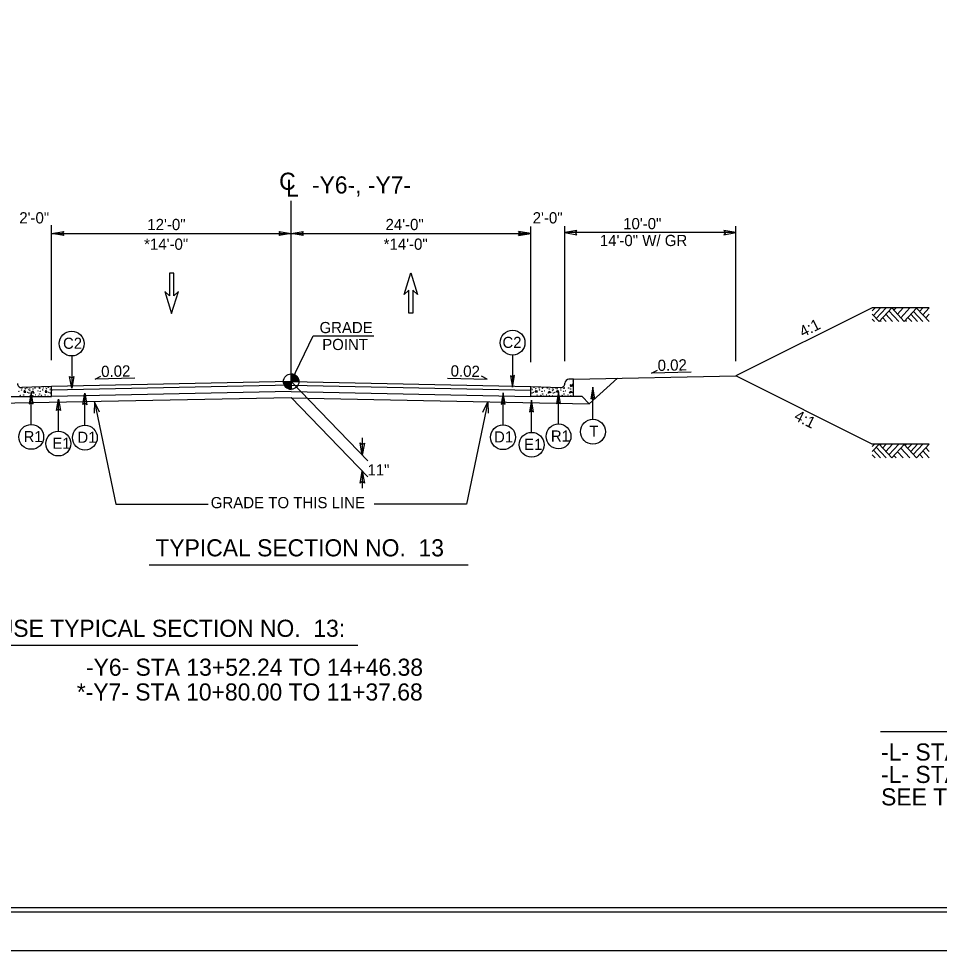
# Model space of a CAD drawing. Extents: x 1901670 to 1902225, y 193498 to 194278.
# Drawn here: x 1902009.7 to 1902063.5, y 193498 to 193552.5 of the extents above; entities that cross this region are included whole.
import ezdxf

# ---------------------------------------------------------------- set-up
doc = ezdxf.new("R2010")
doc.units = 0
for name, color, linetype in [('Old_Level_1', 7, 'Continuous'), ('Old_Level_11', 7, 'Continuous'), ('Old_Level_2', 7, 'Continuous'), ('Old_Level_20', 7, 'Continuous'), ('Prop Dimension', 7, 'Continuous'), ('Sheet Border Standard 30in CELL', 7, 'Continuous'), ('Sheet Cutting Line CELL', 7, 'Continuous'), ('Sheet Plot Border Inside CELL', 7, 'Continuous'), ('Sheet Plot Border Outside CELL', 7, 'Continuous'), ('Typical Curb CELL', 7, 'Continuous'), ('Typical Pavement Slope CELL', 7, 'Continuous'), ('Typical Terminator CELL', 7, 'Continuous'), ('Typical Text Grade Point CELL', 7, 'Continuous')]:
    doc.layers.add(name, color=color, linetype=linetype)

# ---------------------------------------------------------------- blocks, each defined once
blk = doc.blocks.new('TERMINATOR')
at = {"layer": 'Typical Terminator CELL'}
blk.add_lwpolyline([(-0.469, 0.081), (0, 0), (-0.471, -0.083), (-0.411, 0)], close=True, dxfattribs=at)

msp = doc.modelspace()

# ---------------------------------------------------------------- linework, layer by layer
at = {"layer": 'Old_Level_1'}
for p, q in [((1902025.621, 193531.249), (1902025.621, 193541.807)), ((1902059.748, 193535.554), (1902059.578, 193535.371)), ((1902060.068, 193535.554), (1902059.654, 193535.11)), ((1902060.401, 193535.554), (1902059.821, 193534.931)), ((1902060.723, 193535.553), (1902059.982, 193534.757)), ((1902061.144, 193534.749), (1902060.558, 193535.377)), ((1902061.454, 193534.767), (1902060.723, 193535.553)), ((1902060.987, 193535.554), (1902060.854, 193535.411)), ((1902061.389, 193535.554), (1902061.056, 193535.195)), ((1902061.787, 193535.554), (1902061.254, 193534.981)), ((1902062.178, 193535.546), (1902061.454, 193534.767)), ((1902062.546, 193534.749), (1902061.992, 193535.345)), ((1902062.92, 193534.749), (1902062.178, 193535.546)), ((1902062.545, 193535.554), (1902062.358, 193535.353)), ((1902062.92, 193535.554), (1902062.545, 193535.151)), ((1902059.982, 193534.757), (1902059.578, 193535.192)), ((1902059.712, 193534.749), (1902059.578, 193534.892)), ((1902060.113, 193534.749), (1902060.044, 193534.823)), ((1902060.408, 193534.749), (1902060.191, 193534.982)), ((1902060.774, 193534.749), (1902060.374, 193535.178)), ((1902061.579, 193534.749), (1902061.508, 193534.825)), ((1902061.89, 193534.749), (1902061.663, 193534.992)), ((1902062.237, 193534.749), (1902061.836, 193535.178)), ((1902062.92, 193535.192), (1902062.714, 193534.97)), ((1902014.167, 193531.391), (1902014.5, 193531.558)), ((1902016.482, 193531.44), (1902014.167, 193531.391)), ((1902025.621, 193531.249), (1902025.621, 193531.699)), ((1902034.759, 193531.44), (1902037.074, 193531.391)), ((1902037.074, 193531.391), (1902036.741, 193531.558)), ((1902044.701, 193531.437), (1902043.043, 193529.952)), ((1902046.691, 193531.746), (1902047.024, 193531.913)), ((1902049.006, 193531.794), (1902046.691, 193531.746)), ((1902025.621, 193531.249), (1902011.621, 193530.969)), ((1902025.621, 193531.03), (1902011.621, 193530.75)), ((1902025.171, 193531.249), (1902025.621, 193531.249)), ((1902025.62, 193530.799), (1902025.621, 193531.249)), ((1902025.621, 193531.249), (1902025.62, 193530.799)), ((1902025.621, 193531.249), (1902030.097, 193526.624)), ((1902026.071, 193531.249), (1902025.621, 193531.249)), ((1902025.621, 193531.249), (1902039.621, 193530.969)), ((1902025.621, 193531.03), (1902039.621, 193530.75)), ((1902025.621, 193530.301), (1902008.198, 193529.952)), ((1902025.621, 193530.665), (1902011.621, 193530.385)), ((1902025.621, 193530.665), (1902039.621, 193530.385)), ((1902025.621, 193530.301), (1902043.043, 193529.952)), ((1902025.623, 193530.314), (1902030.099, 193525.689)), ((1902042.62, 193530.375), (1902042.12, 193530.385)), ((1902042.62, 193530.375), (1902043.043, 193529.952)), ((1902029.778, 193527.953), (1902029.778, 193526.953)), ((1902059.712, 193527.597), (1902059.578, 193527.454)), ((1902059.982, 193527.589), (1902059.578, 193527.154)), ((1902060.723, 193526.793), (1902059.982, 193527.589)), ((1902060.113, 193527.597), (1902060.044, 193527.523)), ((1902060.408, 193527.597), (1902060.191, 193527.364)), ((1902060.774, 193527.597), (1902060.374, 193527.168)), ((1902061.144, 193527.597), (1902060.558, 193526.969)), ((1902061.579, 193527.597), (1902061.508, 193527.521)), ((1902061.89, 193527.597), (1902061.663, 193527.354)), ((1902062.237, 193527.597), (1902061.836, 193527.168)), ((1902062.546, 193527.597), (1902061.992, 193527.001)), ((1902062.92, 193527.597), (1902062.178, 193526.8)), ((1902060.068, 193526.792), (1902059.654, 193527.236)), ((1902060.401, 193526.792), (1902059.821, 193527.415)), ((1902061.454, 193527.579), (1902060.723, 193526.793)), ((1902061.389, 193526.792), (1902061.056, 193527.151)), ((1902061.787, 193526.792), (1902061.254, 193527.365)), ((1902062.178, 193526.8), (1902061.454, 193527.579)), ((1902062.92, 193526.792), (1902062.545, 193527.195)), ((1902062.92, 193527.154), (1902062.714, 193527.376)), ((1902059.748, 193526.792), (1902059.578, 193526.975)), ((1902060.987, 193526.792), (1902060.854, 193526.935)), ((1902062.545, 193526.792), (1902062.358, 193526.993)), ((1902029.78, 193526.019), (1902029.78, 193525.019))]:
    msp.add_line(p, q, dxfattribs=at)
for points in [[(1902025.625, 193531.699), (1902025.625, 193531.699), (1902025.625, 193531.249)], [(1902025.634, 193531.699), (1902025.634, 193531.249)], [(1902025.643, 193531.698), (1902025.643, 193531.249)], [(1902025.652, 193531.698), (1902025.652, 193531.249)], [(1902025.661, 193531.697), (1902025.661, 193531.249)], [(1902025.67, 193531.696), (1902025.67, 193531.249)], [(1902025.679, 193531.695), (1902025.679, 193531.249)], [(1902025.688, 193531.694), (1902025.688, 193531.249)], [(1902025.697, 193531.693), (1902025.697, 193531.249)], [(1902025.706, 193531.691), (1902025.706, 193531.249)], [(1902025.715, 193531.689), (1902025.715, 193531.249)], [(1902025.724, 193531.687), (1902025.724, 193531.249)], [(1902025.733, 193531.685), (1902025.733, 193531.249)], [(1902025.742, 193531.682), (1902025.742, 193531.249)], [(1902025.751, 193531.68), (1902025.751, 193531.249)], [(1902025.76, 193531.677), (1902025.76, 193531.249)], [(1902025.769, 193531.674), (1902025.769, 193531.249)], [(1902025.778, 193531.671), (1902025.778, 193531.249)], [(1902025.787, 193531.667), (1902025.787, 193531.249)], [(1902025.796, 193531.663), (1902025.796, 193531.249)], [(1902025.805, 193531.659), (1902025.805, 193531.249)], [(1902025.814, 193531.655), (1902025.814, 193531.249)], [(1902025.823, 193531.651), (1902025.823, 193531.249)], [(1902025.832, 193531.646), (1902025.832, 193531.249)], [(1902025.841, 193531.641), (1902025.841, 193531.249)], [(1902025.85, 193531.636), (1902025.85, 193531.249)], [(1902025.859, 193531.631), (1902025.859, 193531.249)], [(1902025.868, 193531.625), (1902025.868, 193531.249)], [(1902025.877, 193531.619), (1902025.877, 193531.249)], [(1902025.886, 193531.612), (1902025.886, 193531.249)], [(1902025.895, 193531.606), (1902025.895, 193531.249)], [(1902025.904, 193531.599), (1902025.904, 193531.249)], [(1902025.913, 193531.591), (1902025.913, 193531.249)], [(1902025.922, 193531.583), (1902025.922, 193531.249)], [(1902025.931, 193531.575), (1902025.931, 193531.249)], [(1902025.94, 193531.566), (1902025.94, 193531.249)], [(1902025.949, 193531.557), (1902025.949, 193531.249)], [(1902025.958, 193531.547), (1902025.958, 193531.249)], [(1902025.967, 193531.536), (1902025.967, 193531.249)], [(1902025.976, 193531.525), (1902025.976, 193531.249)], [(1902025.985, 193531.513), (1902025.985, 193531.249)], [(1902025.994, 193531.5), (1902025.994, 193531.249)], [(1902026.003, 193531.486), (1902026.003, 193531.249)], [(1902026.012, 193531.471), (1902026.012, 193531.249)], [(1902026.021, 193531.455), (1902026.021, 193531.249)], [(1902026.03, 193531.436), (1902026.03, 193531.249)], [(1902026.039, 193531.415), (1902026.039, 193531.249)], [(1902026.048, 193531.39), (1902026.048, 193531.249)], [(1902025.173, 193531.249), (1902025.173, 193531.2)], [(1902025.182, 193531.249), (1902025.182, 193531.147)], [(1902025.191, 193531.249), (1902025.191, 193531.115)], [(1902025.2, 193531.249), (1902025.2, 193531.088)], [(1902025.209, 193531.249), (1902025.209, 193531.067)], [(1902025.218, 193531.249), (1902025.218, 193531.048)], [(1902025.227, 193531.249), (1902025.227, 193531.031)], [(1902025.236, 193531.249), (1902025.236, 193531.015)], [(1902025.245, 193531.249), (1902025.245, 193531.001)], [(1902025.254, 193531.249), (1902025.254, 193530.988)], [(1902025.263, 193531.249), (1902025.263, 193530.976)], [(1902025.272, 193531.249), (1902025.272, 193530.965)], [(1902025.281, 193531.249), (1902025.281, 193530.954)], [(1902025.29, 193531.249), (1902025.29, 193530.944)], [(1902025.299, 193531.249), (1902025.299, 193530.934)], [(1902025.308, 193531.249), (1902025.308, 193530.925)], [(1902025.317, 193531.249), (1902025.317, 193530.917)], [(1902025.326, 193531.249), (1902025.326, 193530.909)], [(1902025.335, 193531.249), (1902025.335, 193530.901)], [(1902025.344, 193531.249), (1902025.344, 193530.894)], [(1902025.353, 193531.249), (1902025.353, 193530.887)], [(1902025.362, 193531.249), (1902025.362, 193530.881)], [(1902025.371, 193531.249), (1902025.371, 193530.875)], [(1902025.38, 193531.249), (1902025.38, 193530.869)], [(1902025.389, 193531.249), (1902025.389, 193530.863)], [(1902025.398, 193531.249), (1902025.398, 193530.858)], [(1902025.407, 193531.249), (1902025.407, 193530.853)], [(1902025.416, 193531.249), (1902025.416, 193530.848)], [(1902025.425, 193531.249), (1902025.425, 193530.844)], [(1902025.434, 193531.249), (1902025.434, 193530.84)], [(1902025.443, 193531.249), (1902025.443, 193530.836)], [(1902025.452, 193531.249), (1902025.452, 193530.832)], [(1902025.461, 193531.249), (1902025.461, 193530.828)], [(1902025.47, 193531.249), (1902025.47, 193530.825)], [(1902025.479, 193531.249), (1902025.479, 193530.822)], [(1902025.488, 193531.249), (1902025.488, 193530.819)], [(1902025.497, 193531.249), (1902025.497, 193530.817)], [(1902025.506, 193531.249), (1902025.506, 193530.814)], [(1902025.515, 193531.249), (1902025.515, 193530.812)], [(1902025.524, 193531.249), (1902025.524, 193530.81)], [(1902025.533, 193531.249), (1902025.533, 193530.808)], [(1902025.542, 193531.249), (1902025.542, 193530.806)], [(1902025.551, 193531.249), (1902025.551, 193530.805)], [(1902025.56, 193531.249), (1902025.56, 193530.803)], [(1902025.569, 193531.249), (1902025.569, 193530.802)], [(1902025.578, 193531.249), (1902025.578, 193530.801)], [(1902025.587, 193531.249), (1902025.587, 193530.8)], [(1902025.596, 193531.249), (1902025.596, 193530.8)], [(1902025.605, 193531.249), (1902025.605, 193530.799)], [(1902025.614, 193531.249), (1902025.614, 193530.799), (1902025.614, 193530.799)], [(1902026.057, 193531.359), (1902026.057, 193531.249)], [(1902026.066, 193531.313), (1902026.066, 193531.249)], [(1902014.419, 193529.462), (1902014.126, 193530.071), (1902014.098, 193529.395)], [(1902014.126, 193530.071), (1902015.376, 193524.093), (1902020.767, 193524.093)], [(1902037.116, 193530.071), (1902035.865, 193524.093), (1902030.474, 193524.093)], [(1902036.822, 193529.462), (1902037.116, 193530.071), (1902037.143, 193529.395)]]:
    msp.add_lwpolyline(points, dxfattribs=at)
msp.add_circle((1902025.62, 193531.248), 0.45, dxfattribs=at)
for start, end in [(359.9905, 89.9905), (179.9905, 269.9905)]:
    msp.add_arc((1902025.62, 193531.248), 0.45, start, end, dxfattribs=at)
at = {"layer": 'Old_Level_11'}
for p, q in [((1902012.793, 193532.742), (1902012.793, 193530.868)), ((1902038.562, 193532.794), (1902038.562, 193530.92)), ((1902043.259, 193529.042), (1902043.259, 193530.917)), ((1902010.429, 193528.739), (1902010.429, 193530.613)), ((1902013.564, 193528.698), (1902013.564, 193530.572)), ((1902038.006, 193528.72), (1902038.006, 193530.594)), ((1902041.249, 193528.77), (1902041.249, 193530.645)), ((1902012.014, 193528.349), (1902012.014, 193530.223)), ((1902039.675, 193528.281), (1902039.675, 193530.156)), ((1902017.328, 193520.54), (1902033.954, 193520.54)), ((1902018.328, 193520.54), (1902035.974, 193520.54)), ((1902008.39, 193515.839), (1902029.517, 193515.839)), ((1902060.068, 193510.801), (1902091.616, 193510.801))]:
    msp.add_line(p, q, dxfattribs=at)
for points in [[(1902012.908, 193531.539), (1902012.793, 193530.868), (1902012.673, 193531.543), (1902012.793, 193531.457)], [(1902038.447, 193531.591), (1902038.562, 193530.92), (1902038.682, 193531.595), (1902038.562, 193531.509)], [(1902043.375, 193530.245), (1902043.259, 193530.917), (1902043.14, 193530.241), (1902043.259, 193530.327)], [(1902010.545, 193529.942), (1902010.429, 193530.613), (1902010.31, 193529.938), (1902010.429, 193530.024)], [(1902013.449, 193529.901), (1902013.564, 193530.572), (1902013.684, 193529.897), (1902013.564, 193529.983)], [(1902038.121, 193529.922), (1902038.006, 193530.594), (1902037.886, 193529.919), (1902038.006, 193530.004)], [(1902041.365, 193529.973), (1902041.249, 193530.645), (1902041.13, 193529.969), (1902041.249, 193530.055)], [(1902011.898, 193529.552), (1902012.014, 193530.223), (1902012.133, 193529.548), (1902012.014, 193529.634)], [(1902039.79, 193529.484), (1902039.675, 193530.156), (1902039.555, 193529.48), (1902039.675, 193529.566)]]:
    msp.add_lwpolyline(points, close=True, dxfattribs=at)
for centre in [(1902012.793, 193533.467), (1902038.562, 193533.519), (1902010.429, 193528.014), (1902013.564, 193527.973), (1902038.006, 193527.994), (1902041.249, 193528.045), (1902043.259, 193528.317), (1902012.014, 193527.624), (1902039.675, 193527.556)]:
    msp.add_circle(centre, 0.725, dxfattribs=at)
at = {"layer": 'Prop Dimension'}
for p, q in [((1902011.621, 193532.496), (1902011.621, 193540.379)), ((1902039.621, 193532.426), (1902039.621, 193540.309)), ((1902039.621, 193532.386), (1902039.621, 193540.229)), ((1902041.621, 193532.436), (1902041.621, 193540.319)), ((1902051.621, 193532.436), (1902051.621, 193540.319)), ((1902011.621, 193539.899), (1902025.621, 193539.899)), ((1902025.621, 193539.899), (1902039.621, 193539.899)), ((1902051.621, 193539.949), (1902041.621, 193539.949))]:
    msp.add_line(p, q, dxfattribs=at)
for points in [[(1902019.027, 193536.501), (1902018.756, 193536.251), (1902018.756, 193537.585), (1902018.506, 193537.585), (1902018.506, 193536.251), (1902018.235, 193536.501), (1902018.631, 193535.231)], [(1902019.027, 193536.501), (1902018.756, 193536.251), (1902018.756, 193537.585), (1902018.506, 193537.585), (1902018.506, 193536.251), (1902018.235, 193536.501), (1902018.631, 193535.231)], [(1902033.012, 193536.335), (1902032.741, 193536.585), (1902032.741, 193535.252), (1902032.491, 193535.252), (1902032.491, 193536.585), (1902032.221, 193536.335), (1902032.616, 193537.606)], [(1902033.012, 193536.335), (1902032.741, 193536.585), (1902032.741, 193535.252), (1902032.491, 193535.252), (1902032.491, 193536.585), (1902032.221, 193536.335), (1902032.616, 193537.606)]]:
    msp.add_lwpolyline(points, close=True, dxfattribs=at)
at = {"layer": 'Sheet Border Standard 30in CELL'}
msp.add_lwpolyline([(1902132.544, 193605.514), (1901982.544, 193605.514), (1901982.544, 193500.514), (1902132.544, 193500.514)], close=True, dxfattribs=at)
at = {"layer": 'Sheet Cutting Line CELL'}
msp.add_line((1901965.844, 193498.014), (1902134.244, 193498.014), dxfattribs=at)
at = {"layer": 'Sheet Plot Border Inside CELL'}
msp.add_lwpolyline([(1902133.794, 193605.769), (1901967.144, 193605.769), (1901967.144, 193500.259), (1902133.794, 193500.259)], close=True, dxfattribs=at)
at = {"layer": 'Sheet Plot Border Outside CELL'}
msp.add_lwpolyline([(1902134.244, 193608.014), (1901965.844, 193608.014), (1901965.844, 193498.014), (1902134.244, 193498.014)], close=True, dxfattribs=at)
at = {"layer": 'Typical Curb CELL'}
for p, q in [((1902011.621, 193530.969), (1902009.87, 193530.896)), ((1902011.621, 193530.385), (1902011.621, 193530.969)), ((1902039.621, 193530.385), (1902039.621, 193530.969)), ((1902039.621, 193530.969), (1902041.371, 193530.896)), ((1902041.62, 193531.135), (1902041.62, 193531.146)), ((1902042.12, 193531.385), (1902041.86, 193531.385)), ((1902041.93, 193531.052), (1902041.946, 193530.961)), ((1902042.084, 193531.007), (1902041.93, 193531.052)), ((1902041.946, 193530.961), (1902042.084, 193531.007)), ((1902042.12, 193530.385), (1902042.12, 193531.385)), ((1902009.121, 193530.385), (1902011.621, 193530.385)), ((1902010.025, 193530.745), (1902009.991, 193530.631)), ((1902009.991, 193530.631), (1902010.11, 193530.625)), ((1902010.11, 193530.625), (1902010.025, 193530.745)), ((1902010.532, 193530.688), (1902010.429, 193530.613)), ((1902010.429, 193530.613), (1902010.595, 193530.574)), ((1902010.595, 193530.574), (1902010.532, 193530.688)), ((1902011.274, 193530.745), (1902011.239, 193530.631)), ((1902011.239, 193530.631), (1902011.36, 193530.625)), ((1902011.36, 193530.625), (1902011.274, 193530.745)), ((1902042.12, 193530.385), (1902039.621, 193530.385)), ((1902039.881, 193530.625), (1902039.967, 193530.745)), ((1902040.002, 193530.631), (1902039.881, 193530.625)), ((1902039.967, 193530.745), (1902040.002, 193530.631)), ((1902040.646, 193530.574), (1902040.709, 193530.688)), ((1902040.812, 193530.613), (1902040.646, 193530.574)), ((1902040.709, 193530.688), (1902040.812, 193530.613)), ((1902041.131, 193530.625), (1902041.216, 193530.745)), ((1902041.251, 193530.631), (1902041.131, 193530.625)), ((1902041.216, 193530.745), (1902041.251, 193530.631)), ((1902041.895, 193530.574), (1902041.958, 193530.688)), ((1902042.061, 193530.613), (1902041.895, 193530.574)), ((1902041.958, 193530.688), (1902042.061, 193530.613))]:
    msp.add_line(p, q, dxfattribs=at)
for centre in [(1902009.882, 193530.864), (1902010.173, 193530.879), (1902010.652, 193530.87), (1902010.909, 193530.898), (1902010.926, 193530.848), (1902011.131, 193530.864), (1902011.28, 193530.927), (1902011.422, 193530.91), (1902039.819, 193530.91), (1902039.961, 193530.927), (1902040.11, 193530.864), (1902040.315, 193530.848), (1902040.332, 193530.898), (1902040.589, 193530.87), (1902041.068, 193530.879), (1902041.359, 193530.864), (1902041.564, 193530.848), (1902041.582, 193530.898), (1902041.838, 193530.87), (1902041.89, 193531.309), (1902042.055, 193531.092), (1902042.107, 193531.275), (1902009.705, 193530.677), (1902009.785, 193530.437), (1902009.854, 193530.762), (1902009.991, 193530.46), (1902010.076, 193530.825), (1902010.15, 193530.391), (1902010.202, 193530.625), (1902010.282, 193530.785), (1902010.298, 193530.58), (1902010.338, 193530.819), (1902010.355, 193530.722), (1902010.361, 193530.414), (1902010.515, 193530.431), (1902010.532, 193530.819), (1902010.686, 193530.471), (1902010.829, 193530.705), (1902010.863, 193530.408), (1902010.92, 193530.523), (1902010.954, 193530.677), (1902011.034, 193530.437), (1902011.103, 193530.762), (1902011.24, 193530.46), (1902011.325, 193530.825), (1902011.4, 193530.391), (1902011.451, 193530.625), (1902011.531, 193530.785), (1902011.547, 193530.58), (1902011.587, 193530.819), (1902011.604, 193530.722), (1902011.61, 193530.414), (1902039.631, 193530.414), (1902039.637, 193530.722), (1902039.654, 193530.819), (1902039.694, 193530.58), (1902039.71, 193530.785), (1902039.79, 193530.625), (1902039.842, 193530.391), (1902039.916, 193530.825), (1902040.001, 193530.46), (1902040.138, 193530.762), (1902040.207, 193530.437), (1902040.287, 193530.677), (1902040.321, 193530.523), (1902040.378, 193530.408), (1902040.413, 193530.705), (1902040.555, 193530.471), (1902040.709, 193530.819), (1902040.726, 193530.431), (1902040.88, 193530.414), (1902040.886, 193530.722), (1902040.903, 193530.819), (1902040.943, 193530.58), (1902040.959, 193530.785), (1902041.039, 193530.625), (1902041.091, 193530.391), (1902041.165, 193530.825), (1902041.25, 193530.46), (1902041.387, 193530.762), (1902041.456, 193530.437), (1902041.536, 193530.677), (1902041.57, 193530.523), (1902041.627, 193530.408), (1902041.662, 193530.705), (1902041.804, 193530.471), (1902041.958, 193530.819), (1902041.975, 193530.431)]:
    msp.add_circle(centre, 0.00802, dxfattribs=at)
for centre, start, end in [((1902009.86, 193531.135), 180.0002, 272.3846), ((1902041.381, 193531.135), 267.6154, 359.9998), ((1902041.86, 193531.146), 89.9998, 179.9998)]:
    msp.add_arc(centre, 0.24, start, end, dxfattribs=at)
at = {"layer": 'Typical Pavement Slope CELL'}
for p in [(1902059.578, 193535.554), (1902042.12, 193531.385), (1902059.578, 193527.597)]:
    msp.add_line(p, (1902051.621, 193531.575), dxfattribs=at)
for points in [[(1902062.92, 193535.554), (1902059.578, 193535.554)], [(1902062.92, 193527.597), (1902059.578, 193527.597)]]:
    msp.add_lwpolyline(points, dxfattribs=at)
at = {"layer": 'Typical Text Grade Point CELL'}
for p, q in [((1902025.621, 193531.249), (1902026.916, 193533.922)), ((1902026.916, 193533.922), (1902030.454, 193533.922))]:
    msp.add_line(p, q, dxfattribs=at)

# ---------------------------------------------------------------- block references
at = {"layer": 'Old_Level_1', "xscale": 1.5, "yscale": 1.5}
for p, rotation in [((1902029.778, 193526.953), -90), ((1902029.78, 193526.019), 90)]:
    msp.add_blockref('TERMINATOR', p, dxfattribs=dict(at, rotation=rotation))
at = {"layer": 'Prop Dimension', "xscale": 1.5, "rotation": 180}
for p, yscale in [((1902011.621, 193539.899), 1.5), ((1902025.621, 193539.899), 1.5), ((1902041.621, 193539.949), -1.5)]:
    msp.add_blockref('TERMINATOR', p, dxfattribs=dict(at, yscale=yscale))
at = {"layer": 'Prop Dimension', "xscale": 1.5}
for p, yscale in [((1902025.621, 193539.899), 1.5), ((1902039.621, 193539.899), -1.5), ((1902039.621, 193539.899), 1.5), ((1902051.621, 193539.949), -1.5)]:
    msp.add_blockref('TERMINATOR', p, dxfattribs=dict(at, yscale=yscale))

# ---------------------------------------------------------------- texts
at = {"layer": 'Old_Level_1'}
for rotation, p in [(26.5651, (1902055.531, 193533.82)), (333.4349, (1902054.965, 193529.03))]:
    msp.add_text('4:1', height=0.656, rotation=rotation, dxfattribs=at).set_placement(p)
for s, height, p in [('11"', 0.6491, (1902030.088, 193525.762)), ('GRADE TO THIS LINE', 0.656, (1902020.919, 193523.847))]:
    msp.add_text(s, height=height, dxfattribs=at).set_placement(p)
at = {"layer": 'Old_Level_11'}
for s, p in [('TYPICAL SECTION NO.  13', (1902017.684, 193521.034)), ('USE TYPICAL SECTION NO.  13:', (1902008.415, 193516.333)), ('-Y6- STA 13+52.24 TO 14+46.38 ', (1902013.628, 193514.059)), ('*-Y7- STA 10+80.00 TO 11+37.68', (1902013.091, 193512.612)), ('-L- STA 15+00 TO 19+25 RT', (1902060.101, 193509.105)), ('-L- STA 30+98 TO 34+20 LT', (1902060.101, 193507.794)), ('SEE TRANSPORTATION MANAGEMENT PLANS  ', (1902060.101, 193506.483))]:
    msp.add_text(s, height=1, dxfattribs=at).set_placement(p)
at = {"layer": 'Old_Level_2'}
msp.add_text('C', height=1, dxfattribs=at).set_placement((1902024.919, 193542.453))
for s, height, rotation, p in [('L', 1, 359.9469, (1902025.321, 193542.049)), ('-Y6-, -Y7-', 1, 359.9469, (1902026.835, 193542.24)), ('0.02', 0.656, 1.1916, (1902047.047, 193531.865)), ('0.02', 0.656, 1.1916, (1902014.522, 193531.51)), ('0.02', 0.656, 358.8084, (1902034.936, 193531.547))]:
    msp.add_text(s, height=height, rotation=rotation, dxfattribs=at).set_placement(p)
at = {"layer": 'Old_Level_20'}
for s, height, p in [('C2', 0.6491, (1902012.287, 193533.161)), ('C2', 0.6491, (1902037.973, 193533.213)), ('T', 0.649, (1902043.048, 193528.024)), ('R1', 0.6491, (1902009.984, 193527.71)), ('D1', 0.6491, (1902013.131, 193527.669)), ('D1', 0.6491, (1902037.484, 193527.691)), ('R1', 0.6491, (1902040.804, 193527.742)), ('E1', 0.6491, (1902011.668, 193527.32)), ('E1', 0.6491, (1902039.241, 193527.253))]:
    msp.add_text(s, height=height, dxfattribs=at).set_placement(p)
at = {"layer": 'Prop Dimension'}
for s, p in [('2\'-0" ', (1902009.729, 193540.488)), ('12\'-0" ', (1902017.214, 193540.097)), ('24\'-0" ', (1902031.136, 193540.097)), ('2\'-0" ', (1902039.738, 193540.488)), ('10\'-0" ', (1902045.025, 193540.147)), ('*14\'-0" ', (1902017.026, 193538.948)), ('*14\'-0" ', (1902031.026, 193538.948)), ('14\'-0" W/ GR ', (1902043.663, 193539.164))]:
    msp.add_text(s, height=0.656, dxfattribs=at).set_placement(p)
at = {"layer": 'Typical Text Grade Point CELL'}
for s, p in [('GRADE', (1902027.28, 193534.078)), ('POINT', (1902027.437, 193533.089))]:
    msp.add_text(s, height=0.6525, dxfattribs=at).set_placement(p)

doc.saveas('drawing.dxf')
